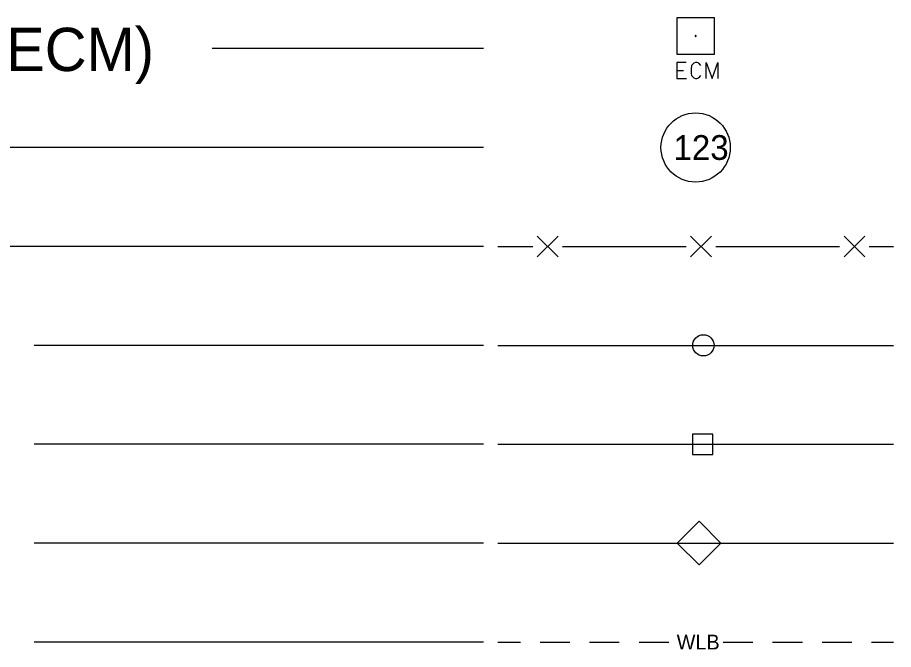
# Model space of a CAD drawing. Extents: x 2594871.4 to 2594905.1, y 784137.6 to 784159.6.
# Drawn here: x 2594878.529 to 2594882.002, y 784151.409 to 784153.916 of the extents above; entities that cross this region are included whole.
import ezdxf

# ---------------------------------------------------------------- set-up
doc = ezdxf.new("R2010")
doc.units = 0
doc.layers.add('Default', color=7, linetype='Continuous')

msp = doc.modelspace()

# ---------------------------------------------------------------- linework, layer by layer
at = {"layer": 'Default'}
for p, q in [((2594880.3766, 784153.7923), (2594879.3012, 784153.7923)), ((2594881.1436, 784153.706), (2594881.1693, 784153.706)), ((2594880.3766, 784153.4), (2594878.4056, 784153.4)), ((2594880.59, 784152.9665), (2594880.6724, 784153.0489)), ((2594880.6724, 784152.9665), (2594880.59, 784153.0489)), ((2594881.198, 784152.9665), (2594881.2804, 784153.0489)), ((2594881.2804, 784152.9665), (2594881.198, 784153.0489)), ((2594881.8061, 784152.9665), (2594881.8885, 784153.0489)), ((2594881.8885, 784152.9665), (2594881.8061, 784153.0489)), ((2594880.3766, 784153.0077), (2594877.5302, 784153.0077)), ((2594880.433, 784153.0077), (2594880.5723, 784153.0077)), ((2594880.69, 784153.0077), (2594880.9352, 784153.0077)), ((2594880.9352, 784153.0077), (2594881.1804, 784153.0077)), ((2594881.2981, 784153.0077), (2594881.5433, 784153.0077)), ((2594881.5433, 784153.0077), (2594881.7885, 784153.0077)), ((2594881.9062, 784153.0077), (2594882.0023, 784153.0077)), ((2594880.3766, 784152.6154), (2594878.5948, 784152.6154)), ((2594880.433, 784152.6154), (2594882.0023, 784152.6154)), ((2594880.433, 784152.6154), (2594882.0023, 784152.6154)), ((2594880.3766, 784152.2231), (2594878.5948, 784152.2231)), ((2594880.433, 784152.2231), (2594882.0023, 784152.2231)), ((2594880.433, 784152.2231), (2594882.0023, 784152.2231)), ((2594880.3766, 784151.8308), (2594878.5948, 784151.8308)), ((2594880.433, 784151.8308), (2594882.0023, 784151.8308)), ((2594880.433, 784151.8308), (2594882.0023, 784151.8308)), ((2594880.3766, 784151.4384), (2594878.5948, 784151.4384)), ((2594880.433, 784151.4384), (2594880.5228, 784151.4384)), ((2594880.6012, 784151.4384), (2594880.7189, 784151.4384)), ((2594880.7974, 784151.4384), (2594880.9151, 784151.4384)), ((2594880.9936, 784151.4384), (2594881.1112, 784151.4384)), ((2594881.327, 784151.4384), (2594881.4447, 784151.4384)), ((2594881.5232, 784151.4384), (2594881.6409, 784151.4384)), ((2594881.7193, 784151.4384), (2594881.837, 784151.4384)), ((2594881.9155, 784151.4384), (2594882.0023, 784151.4384))]:
    msp.add_line(p, q, dxfattribs=at)
for points in [[(2594881.1441, 784153.9157), (2594881.291, 784153.9157), (2594881.291, 784153.7687), (2594881.1441, 784153.7687), (2594881.1441, 784153.9157)], [(2594881.2172, 784153.844), (2594881.2164, 784153.8433), (2594881.2164, 784153.8418), (2594881.2179, 784153.8404), (2594881.2194, 784153.8411), (2594881.2201, 784153.8426), (2594881.2186, 784153.844), (2594881.2172, 784153.844)], [(2594881.1797, 784153.7371), (2594881.1436, 784153.7371), (2594881.1436, 784153.6744), (2594881.1822, 784153.6744)], [(2594881.239, 784153.7248), (2594881.2311, 784153.7352), (2594881.2232, 784153.7371), (2594881.2178, 784153.7371), (2594881.2103, 784153.7352), (2594881.2019, 784153.7248), (2594881.2, 784153.7109), (2594881.2, 784153.7035), (2594881.2, 784153.6986), (2594881.2005, 784153.6941), (2594881.2019, 784153.6862), (2594881.2103, 784153.6763), (2594881.2178, 784153.6744), (2594881.2222, 784153.6744), (2594881.2306, 784153.6763), (2594881.239, 784153.6862)], [(2594881.2593, 784153.6744), (2594881.2593, 784153.7371), (2594881.283, 784153.6744), (2594881.3057, 784153.7371), (2594881.3057, 784153.6744)]]:
    msp.add_lwpolyline(points, dxfattribs=at)
for points in [[(2594881.2054, 784152.1829), (2594881.2858, 784152.1829), (2594881.2858, 784152.2633), (2594881.2054, 784152.2633)], [(2594881.2314, 784151.7444), (2594881.3177, 784151.8308), (2594881.2314, 784151.918), (2594881.1451, 784151.8308)]]:
    msp.add_lwpolyline(points, close=True, dxfattribs=at)
for centre, radius in [((2594881.2177, 784153.4), 0.1373), ((2594881.2486, 784152.6154), 0.0422)]:
    msp.add_circle(centre, radius, dxfattribs=at)

# ---------------------------------------------------------------- texts
for s, height, p in [('Existing Concrete Monument (ECM)', 0.171636, (2594875.3968, 784153.7033)), ('123', 0.09808, (2594881.1299, 784153.351)), ('WLB', 0.05885, (2594881.1426, 784151.409))]:
    msp.add_text(s, height=height, rotation=360, dxfattribs=at).set_placement(p)

doc.saveas('drawing.dxf')
